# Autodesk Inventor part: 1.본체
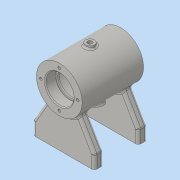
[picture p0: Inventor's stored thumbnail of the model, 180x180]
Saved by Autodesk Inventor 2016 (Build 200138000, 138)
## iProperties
Created: 2018-05
Part Number: 1.본체
Material: 일반
Document SubType Name: Modeling
Designer: 605-04
Density: 1 g/cm^3
Appearance: 기본값
Author: 605-04
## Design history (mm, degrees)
sketch "스케치1"
  geometry: C1 r 26 at (0, 0); 1 further point
  constraints: 1 centre point, 1 coincident
  dimensions: "d0" = 52 diameter of C1
extrude "돌출1" new body sketch "스케치1" stored distance "d1" = 70; taper "d2" = 0 deg
sketch "스케치2"
  geometry: L1 (26, 35)-(-26, 35) reference; L2 (-26, -35)-(26, -35) reference; L3 (0, 35)-(0, -35); L4 (16, 35)-(16, 23); L5 (16, 23)-(14, 23); L6 (14, 23)-(14, 21); L7 (14, 21)-(21, 21); L8 (21, 21)-(21, -21); L9 (21, -21)-(14, -21); L10 (14, -21)-(14, -23); L11 (14, -23)-(16, -23); L12 (16, -23)-(16, -35); L13 (0, 35)-(16, 35); L14 (0, -35)-(16, -35); 1 further point
  constraints: 24 end point, 6 perpendicular, 6 point on line, 2 midpoint, 1 horizontal, 1 parallel, 1 vertical
  dimensions: "d3" = 28 diameter of L6 L3; "d4" = 32 diameter of L4 L3; "d5" = 42 diameter of L8 L3; "d6" = 12 distance of L4.start L4.end; "d7" = 2 distance of L5.end L6.end; "d8" = 12 distance of L11.end L12.end; "d9" = 2 distance of L9.end L10.end
revolve "회전1" sketch "스케치2" stored, may be unused: angle "d10" = 90 deg
node "작업 평면1"
sketch "스케치3"
  geometry: L1 (-17.325, -19.386)-(-35, -50); L2 (-35, -50)-(-35, -65); L3 (-35, -65)-(35, -65); L4 (35, -65)-(35, -50); L5 (35, -50)-(17.325, -19.386); A1 r 26 centre (0, 0) between (-17.325, -19.386) and (17.325, -19.386) reference; 1 further point
  constraints: 10 end point, 2 equal length, 2 perpendicular, 2 point on circle, 1 vertical
  dimensions: "d12" = 15 distance of L3.end L4.end; "d13" = 30 deg angle of L4 L5; "d14" = 30 deg angle of L2 L1 (= d13); "d15" = 70 distance of L2.end L3.end; "d16" = 65 distance from line of L3 point (0, 0)
extrude "돌출2" join sketch "스케치3" distance "d17" = 10; taper "d18" = 0 deg
node "작업 평면2"
sketch "스케치4"
  geometry: L1 (-17.325, -19.386)-(-35, -50); L2 (-35, -50)-(-35, -65); L3 (-35, -65)-(35, -65); L4 (35, -65)-(35, -50); L5 (35, -50)-(17.325, -19.386); A1 r 26 centre (0, 0) between (-17.325, -19.386) and (17.325, -19.386) reference; 1 further point
  constraints: 10 end point, 2 equal length, 2 perpendicular, 2 point on circle, 1 vertical
  dimensions: "d20" = 15 distance of L3.end L4.end; "d21" = 70 distance of L2.end L3.end; "d22" = 30 deg angle of L4 L5; "d23" = 30 deg angle of L1 L2 (= d22); "d24" = 65 distance from line of L3 point (0, 0)
extrude "돌출3" join sketch "스케치4" distance "d25" = 10; taper "d26" = 0 deg
node "작업 평면3"
sketch "스케치5"
  geometry: C1 r 5 at (0, 0); 1 further point
  constraints: 1 centre point, 1 coincident
  dimensions: "d28" = 10 diameter of C1
extrude "돌출4" join sketch "스케치5" stored distance "d29" = 10; taper "d30" = 0 deg
sketch "스케치6"
  geometry: L1 (0, 0)-(0, -26); L2 (0, 0)-(9.919, -27.251); 1 further point
  constraints: 4 end point, 1 vertical, 1 vertical alignment, 1 other
  dimensions: "d31" = 20 deg angle of L2 L1; "d32" = 29 distance of L1.start L2.end
node "작업 평면4"
sketch "스케치7"
  geometry: C1 r 6 at (0, 0); 1 further point
  constraints: 1 centre point, 1 coincident
  dimensions: "d33" = 12 diameter of C1
extrude "돌출5" join sketch "스케치7" stored distance "d34" = 10; taper "d35" = 0 deg
sketch "스케치8" dims "d36" = 42
  geometry: 3 further points
  constraints: 2 vertical alignment, 1 coincident, 2 other
hole "구멍1" sketch "스케치8" at (0, 21) diameter "d37" = 3.242; stored, may be unused: countersink angle "d41" = 90 deg, drill point angle "d43" = 118 deg; dims "d38" = 8, "d39" = 4, "d40" = 2, "d42" = 10
sketch "스케치9"
  geometry: C1 r 21 at (0, 0); C2 r 1.621 at (0, 21) reference; 2 further points
  constraints: 2 coincident, 1 centre point
  dimensions: "d47" = 42 diameter of C1
hole "구멍2" sketch "스케치9" at (0, 21) diameter "d48" = 3.242; stored, may be unused: countersink angle "d52" = 90 deg, drill point angle "d54" = 118 deg; dims "d49" = 8, "d50" = 4, "d51" = 2, "d53" = 10
hole "구멍3" diameter "d60" = 5.188; stored, may be unused: countersink angle "d64" = 90 deg, drill point angle "d66" = 118 deg; dims "d58" = 10, "d59" = 10, "d61" = 12, "d62" = 4, "d63" = 2, "d65" = 16
hole "구멍4" diameter "d69" = 5.188; stored, may be unused: countersink angle "d73" = 90 deg, drill point angle "d75" = 118 deg; dims "d67" = 10, "d68" = 10, "d70" = 12, "d71" = 4, "d72" = 2, "d74" = 16
sketch "스케치10"
  geometry: L1 (0, 50)-(70, 50) reference; L2 (0, 0)-(70, 0) reference; 5 further points
  dimensions: "d76" = 20 horizontal distance of point (55, 45) point (35, 20); "d77" = 5 distance from line of point (55, 45) L1; "d78" = 20 horizontal distance of point (55, -5) point (35, 20) (= d76); "d79" = 20 horizontal distance of point (15, -5) point (35, 20) (= d76); "d80" = 20 horizontal distance of point (15, 45) point (35, 20) (= d76); "d81" = 5 distance from line of point (55, -5) L2 (= d77); "d82" = 5 distance from line of point (15, 45) L1 (= d77); "d83" = 5 distance from line of point (15, -5) L2 (= d77)
hole "구멍5" sketch "스케치10" at (55, 45), (15, 45), (55, -5), (15, -5) diameter "d84" = 4.134; stored, may be unused: countersink angle "d88" = 90 deg, drill point angle "d90" = 118 deg; dims "d85" = 8, "d86" = 4, "d87" = 2, "d89" = 10
chamfer "모따기1" distance "d91" = 1; stored, may be unused: second distance "d92" = 2, angle "d93" = 45 deg
fillet "모깎기1" dims "d94" = 0.3
fillet "모깎기2" dims "d95" = 3
fillet "모깎기3" dims "d96" = 2
fillet "모깎기4" dims "d97" = 3
fillet "모깎기5" dims "d98" = 3
fillet "모깎기6" dims "d99" = 3
node "작업 평면5"
sketch "스케치11"
  geometry: L1 (-26, -35)-(26, -35) reference; 2 further points
  constraints: 1 other
  dimensions: "d100" = 35 distance from line of point (0, 0) L1; "d101" = 26 horizontal distance of L1.start point (0, 0)
feature "엠보싱1" sketch "스케치11" dims "d102" = 0.5, "d103" = 0
node "솔리드1"
pattern_circular "원형 패턴1" dims angle "d45" = 360 deg
pattern_circular "원형 패턴2" dims angle "d56" = 360 deg
other parameters: "d27" = 29
